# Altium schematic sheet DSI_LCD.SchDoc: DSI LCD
size A4; Date: Not used; ApprovedBy: Not used; CheckedBy: Not used; Author: Not used; CompanyName: STMicroelectronics; DrawnBy: Not used; Engineer: Not used; Organization: Not used; Address1: Not used; Address2: Not used; Address3: Not used; Address4: Not used; DocumentNumber: Not used; Revision: Not used; SheetNumber: 10; SheetTotal: 16
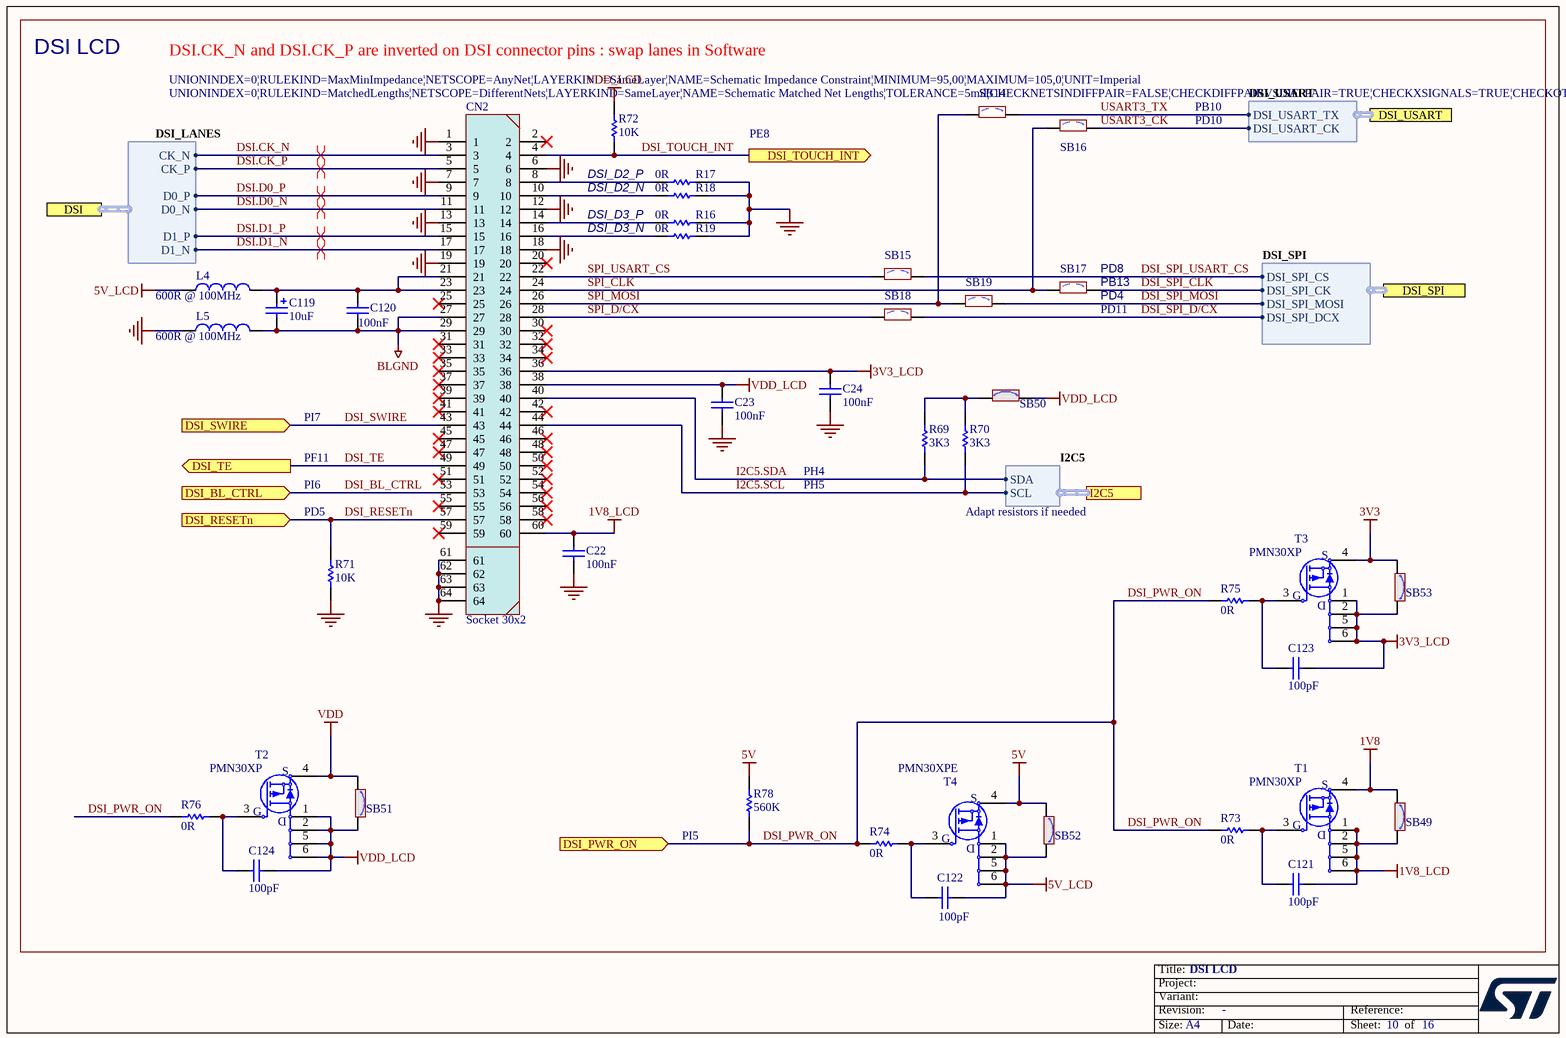
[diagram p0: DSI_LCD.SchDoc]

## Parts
C22  value 100nF  [C0402]  (hidden comment: Capacitor)
C23  value 100nF  [C0402]  (hidden comment: Capacitor)
C24  value 100nF  [C0402]  (hidden comment: Capacitor)
C119  value 10uF  [CPOL_TAJ-A_1206_H180]  (hidden comment: Cap_POL_TANA)
C120  value 100nF  [C0402]  (hidden comment: Capacitor)
C121  value 100pF  [C0603]  (hidden comment: Capacitor)
C122  value 100pF  [C0603]  (hidden comment: Capacitor)
C123  value 100pF  [C0603]  (hidden comment: Capacitor)
C124  value 100pF  [C0603]  (hidden comment: Capacitor)
CN2  value Socket 30x2  [CON_SAMTEC_QSH-030-01-F-D-A_no-LCD-MB1835]  (hidden comment: Socket QSH-030-01-F-D-A_DSI_LCD)
L4  value 600R @ 100MHz  [L0603]  (hidden comment: BEAD)
L5  value 600R @ 100MHz  [L0603]  (hidden comment: BEAD)
R16  value 0R  [R0402]  (hidden comment: Resistor)
R17  value 0R  [R0402]  (hidden comment: Resistor)
R18  value 0R  [R0402]  (hidden comment: Resistor)
R19  value 0R  [R0402]  (hidden comment: Resistor)
R69  value 3K3  [R0402]  (hidden comment: Resistor)
R70  value 3K3  [R0402]  (hidden comment: Resistor)
R71  value 10K  [R0402]  (hidden comment: Resistor)
R72  value 10K  [R0402]  (hidden comment: Resistor)
R73  value 0R  [R0603]  (hidden comment: Resistor)
R74  value 0R  [R0603]  (hidden comment: Resistor)
R75  value 0R  [R0603]  (hidden comment: Resistor)
R76  value 0R  [R0603]  (hidden comment: Resistor)
R78  value 560K  [R0402]  (hidden comment: Resistor)
SB14  SB_OFF  [SOLDER-BRIDGE_R0402-0R]  (value not drawn)
SB15  SB_OFF  [SOLDER-BRIDGE_R0402-0R]  (value not drawn)
SB16  SB_OFF  [SOLDER-BRIDGE_R0402-0R]  (value not drawn)
SB17  SB_OFF  [SOLDER-BRIDGE_R0402-0R]  (value not drawn)
SB18  SB_OFF  [SOLDER-BRIDGE_R0402-0R]  (value not drawn)
SB19  SB_OFF  [SOLDER-BRIDGE_R0402-0R]  (value not drawn)
SB49  SB_ON  [SOLDER-BRIDGE_R0402-0R]  (value not drawn)
SB50  SB_ON  [SOLDER-BRIDGE_R0402-0R]  (value not drawn)
SB51  SB_ON  [SOLDER-BRIDGE_R0402-0R]  (value not drawn)
SB52  SB_ON  [SOLDER-BRIDGE_R0402-0R]  (value not drawn)
SB53  SB_ON  [SOLDER-BRIDGE_R0402-0R]  (value not drawn)
T1  PMN30XP  [MOS_SOT23-6L]
T2  PMN30XP  [MOS_SOT23-6L]
T3  PMN30XP  [MOS_SOT23-6L]
T4  value PMN30XPE  [MOS_TSOP6_CASE-457_P095]  (hidden comment: PMN30XP)

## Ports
DSI (harness DSI_LANES), DSI_BL_CTRL (in), DSI_PWR_ON (in), DSI_RESETn (in), DSI_SPI (harness DSI_SPI), DSI_SWIRE (in), DSI_TE (out), DSI_TOUCH_INT (out), DSI_USART (harness DSI_USART), I2C5 (harness I2C5)

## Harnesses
I2C5: SDA, SCL
DSI_USART: DSI_USART_CK, DSI_USART_TX
DSI_SPI: DSI_SPI_CS, DSI_SPI_MOSI, DSI_SPI_CK, DSI_SPI_DCX
DSI_LANES: CK_P, CK_N, D0_P, D0_N, D1_N, D1_P

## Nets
1V8: SB49.1 T1.4(S)
1V8_LCD: C22.2 C121.2 CN2.60 SB49.2 T1.1(S) T1.2(S) T1.5(D) T1.6(D)
3V3: SB53.1 T3.4(S)
3V3_LCD: C24.2 C123.2 CN2.36 SB53.2 T3.1(S) T3.2(S) T3.5(D) T3.6(D)
5V: R78.2 SB52.1 T4.4(S)
5V_LCD: C122.2 L4.1 SB52.2 T4.1(S) T4.2(S) T4.5(D) T4.6(D)
BLGND: C119.2 C120.1 CN2.27 CN2.29 L5.2
GND: C22.1 C23.1 C24.1 CN2.1 CN2.6 CN2.7 CN2.12 CN2.13 CN2.18 CN2.19 CN2.61 CN2.62 CN2.63 CN2.64 L5.1 R16.2 R17.2 R18.2 R19.2 R71.1
VDD: SB51.1 T2.4(S)
VDD_LCD: C23.2 C124.2 CN2.38 R72.2 SB50.2 SB51.2 T2.1(S) T2.2(S) T2.5(D) T2.6(D)
DSI.CK_N: CN2.3 ; port DSI.CK_N
DSI.CK_P: CN2.5 ; port DSI.CK_P
DSI.D0_N: CN2.11 ; port DSI.D0_N
DSI.D0_P: CN2.9 ; port DSI.D0_P
DSI.D1_N: CN2.17 ; port DSI.D1_N
DSI.D1_P: CN2.15 ; port DSI.D1_P
DSI_BL_CTRL: CN2.53 ; port DSI_BL_CTRL
DSI_PWR_ON: R73.1 R74.1 R75.1 R76.1 R78.1 ; port DSI_PWR_ON
DSI_RESETn: CN2.57 R71.2 ; port DSI_RESETn
DSI_SPI_CLK: SB17.2 ; port DSI_SPI.DSI_SPI_CK
DSI_SPI_D/CX: SB18.2 ; port DSI_SPI.DSI_SPI_DCX
DSI_SPI_MOSI: SB19.2 ; port DSI_SPI.DSI_SPI_MOSI
DSI_SPI_USART_CS: SB15.2 ; port DSI_SPI.DSI_SPI_CS
DSI_SWIRE: CN2.43 ; port DSI_SWIRE
DSI_TE: CN2.49 ; port DSI_TE
DSI_TOUCH_INT: CN2.4 R72.1 ; port DSI_TOUCH_INT
I2C5.SCL: CN2.44 R70.2 ; port I2C5.SCL
I2C5.SDA: CN2.40 R69.2 ; port I2C5.SDA
SPI_CLK: CN2.24 SB16.1 SB17.1
SPI_D/CX: CN2.28 SB18.1
SPI_MOSI: CN2.26 SB14.1 SB19.1
SPI_USART_CS: CN2.22 SB15.1
USART3_CK: SB16.2 ; port DSI_USART.DSI_USART_CK
USART3_TX: SB14.2 ; port DSI_USART.DSI_USART_TX
NetC119_1: C119.1 C120.2 CN2.21 CN2.23 L4.2
NetC121_1: C121.1 R73.2 T1.3(G)
NetC122_1: C122.1 R74.2 T4.3(G)
NetC123_1: C123.1 R75.2 T3.3(G)
NetC124_1: C124.1 R76.2 T2.3(G)
NetCN2_8: CN2.8 R17.1
NetCN2_10: CN2.10 R18.1
NetCN2_14: CN2.14 R16.1
NetCN2_16: CN2.16 R19.1
NetR69_1: R69.1 R70.1 SB50.1

Not connected (* = marked no-connect by the designer): CN2 2* 20* 25* 30* 31* 32* 33* 34* 35* 37* 39* 41* 42* 45* 46* 47* 48* 50* 51* 52* 54* 55* 56* 58* 59*

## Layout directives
differential pair; rule Impedance Constraint [Min = 95.00    Max = 105.0    ]; rule Matched Net Lengths [Tolerance = 5mil]: DSI.CK_N
differential pair; rule Impedance Constraint [Min = 95.00    Max = 105.0    ]; rule Matched Net Lengths [Tolerance = 0mil]: DSI.CK_P, DSI.D0_N, DSI.D0_P, DSI.D1_N, DSI.D1_P

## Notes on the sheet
- DSI LCD
- DSI.CK_N and DSI.CK_P are inverted on DSI connector pins : swap lanes in Software
- PB10
- DSI_D2_P
- PE8
- PD10
- DSI_D2_N
- DSI_D3_P
- DSI_D3_N
- (near SB17) PD11
- (near SB17) PD4
- (near SB17) PD8
- (near SB17) PB13
- PI7
- PI6
- PF11
- (near R71) PD5
- PH5
- PH4
- Adapt resistors if needed
- (near R78) PI5

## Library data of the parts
C22-C24 C120 = MCD-00006: Capacitor, MLCC, 100nF, 16V, X7R, +/-10%, 0402, T=0.5mm; Manufacturer_Part_Number: CC0402KRX7R7BB104; Manufacturer: YAGEO; Part_Preference: Recommended; Order_Code_RS: 616-9701; Component_Country_Of_Origin: China
C119 = MCD-00199: Capacitor, Tantalum, 10uF, 16V, 3R, +/-10%, Type_A (3216 metric), T=1.6mm; Manufacturer_Part_Number: TAJA106K016R; Manufacturer: AVX; BMS_Part_Number: 9141044; Part_Preference: Recommended; Order_Code_RS: 699-2848; Component_Country_Of_Origin: El Salvador
C121-C124 = MCD-01101: Capacitor, MLCC, 100pF, 50V, X7R, +/-5%, 0603, T=0.33mm; Manufacturer_Part_Number: 06035C101JAT4A; Manufacturer: AVX; Part_Preference: Recommended; Component_Country_Of_Origin: China
CN2 = MCD-02128: Socket, 30x2, 0.5mm, VR, SMD, T=3.05mm; Part_Type: Connector; Manufacturer: SAMTEC; Part_Preference: Recommended; Order_Code_RS: 180-2587; Component_Country_Of_Origin: China, Costa Rica, Malaysia, United States, Vietnam
L4 L5 = MCD-00047: Ferrite bead, 600R @1 00MHz, +/-25%, 350mA, 0R5, 0603, T=0.8mm; Part_Type: Inductor; Manufacturer_Part_Number: FCM1608KF-601T03; Manufacturer: TAI-TECH; Part_Preference: Recommended; Component_Country_Of_Origin: Unknown
R16-R19 = MCD-00052: Resistor, 0R, 0402, +/-5%, 1/16W; Manufacturer_Part_Number: RC0402JR-070RL; Manufacturer: YAGEO; Part_Preference: Recommended; Order_Code_RS: 618-5804; Component_Country_Of_Origin: China
R69 R70 = MCD-00184: Resistor, 3K3, 0402, +/-1%, 1/16W; BMS_Part_Number: 9131946; Manufacturer: YAGEO; Manufacturer_Part_Number: RC0402FR-073K3L; Part_Preference: Recommended; Component_Country_Of_Origin: China
R71 R72 = MCD-00053: Resistor, 10K, 0402, +/-1%, 1/16W; Manufacturer_Part_Number: RC0402FR-0710KL; Manufacturer: YAGEO; BMS_Part_Number: 9131590; Part_Preference: Recommended; Component_Country_Of_Origin: China
R73-R76 = MCD-00056: Resistor, 0R, 0603, +/-5%, 1/10W; Manufacturer_Part_Number: RC0603JR-070RL; Manufacturer: YAGEO; Part_Preference: Recommended; Component_Country_Of_Origin: China
R78 = MCD-00495: Resistor, 560K, 0402, +/-1%, 1/16W; Manufacturer_Part_Number: RC0402FR-07560KL; Manufacturer: YAGEO; Part_Preference: Recommended; Component_Country_Of_Origin: China; ShowFields: YES; ID: 2779
SB14-SB19 = MCD-02162: Solder Bridge 0402 OFF; Part_Type: Misc; Manufacturer_Part_Number: RC0402JR-070RL; Manufacturer: YAGEO; Part_Preference: Recommended; Order_Code_RS: 618-5804; Component_Country_Of_Origin: China
SB49-SB53 = MCD-01618: Solder Bridge 0402 ON; Part_Type: Misc; Manufacturer_Part_Number: RC0402JR-070RL; Manufacturer: YAGEO; Part_Preference: Recommended; Order_Code_RS: 618-5804; Component_Country_Of_Origin: China
T1-T3 = MCD-01926: 20 V, P-channel Trench MOSFET; Part_Type: IC; Manufacturer_Part_Number: PMN30XPX; Manufacturer: NEXPERIA; Part_Preference: Recommended; Order_Code_RS: 153-0671; Component_Country_Of_Origin: China
T4 = MCD-03170: Transistor, MOSFET, P-CH, -20V, 7A, SOT457; Part_Preference: Recommended; Manufacturer: NEXPERIA; Partial_Alternate_Internal_Part_Number: MCD-01926; ShowFields: YES; ID: 5286; Component_Country_Of_Origin: China°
